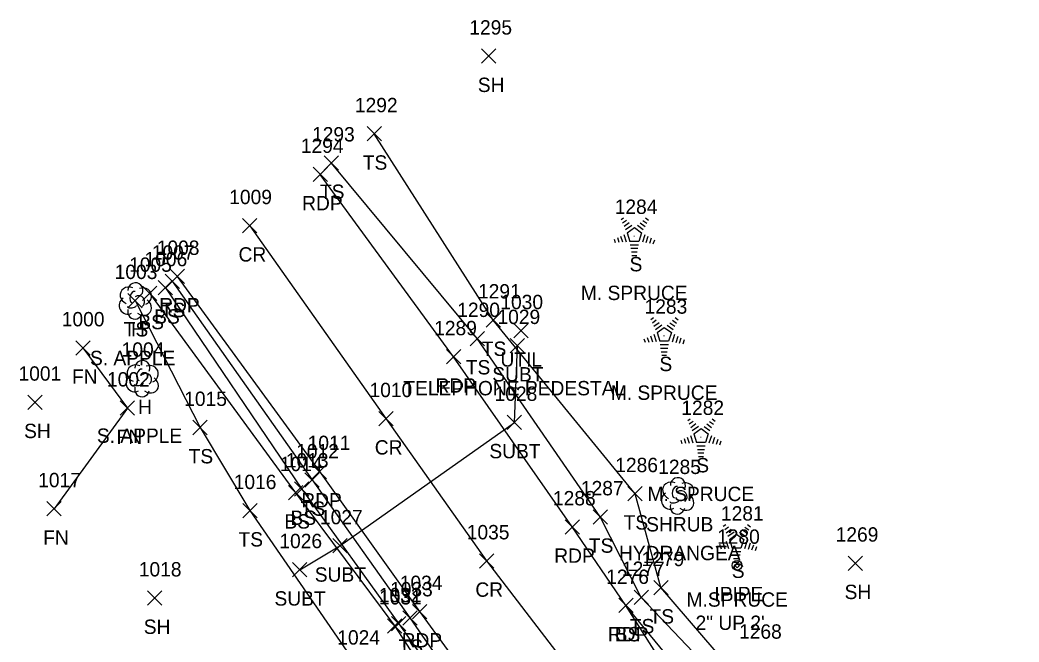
# Model space of a CAD drawing. Extents: x 1761340 to 1763889, y 696770 to 706023.
# Drawn here: x 1761339.7 to 1761478.8, y 701000.1 to 701086.8 of the extents above; entities that cross this region are included whole.
import ezdxf

# ---------------------------------------------------------------- set-up
doc = ezdxf.new("R2010")
doc.units = 0
for name, color, linetype in [('L_A', 7, 'Continuous'), ('L_C', 7, 'Continuous'), ('L_I', 7, 'Continuous'), ('L_TIC', 7, 'Continuous'), ('LELB', 7, 'Continuous'), ('LFNC', 7, 'Continuous'), ('LSH', 7, 'Continuous'), ('LTC', 7, 'Continuous'), ('LTD', 7, 'Continuous'), ('M_A', 7, 'Continuous'), ('M_C', 7, 'Continuous'), ('M_I', 7, 'Continuous'), ('MPIP', 7, 'Continuous'), ('P_A', 7, 'Continuous'), ('P_I', 7, 'Continuous'), ('P_TIC', 7, 'Continuous'), ('PET', 7, 'Continuous'), ('PRC', 7, 'Continuous'), ('U_A', 7, 'Continuous'), ('U_C', 7, 'Continuous'), ('U_I', 7, 'Continuous'), ('U_TIC', 7, 'Continuous'), ('UDEFAULT', 7, 'Continuous'), ('UT', 7, 'Continuous')]:
    doc.layers.add(name, color=color, linetype=linetype)

msp = doc.modelspace()

# ---------------------------------------------------------------- linework, layer by layer
at = {"layer": 'L_TIC'}
for points in [[(1761403.93, 701080.76), (1761405.93, 701082.76)], [(1761405.93, 701080.76), (1761403.93, 701082.76)], [(1761387.99, 701069.94), (1761389.99, 701071.94)], [(1761389.99, 701069.94), (1761387.99, 701071.94)], [(1761382.02, 701065.87), (1761384.02, 701067.87)], [(1761384.02, 701065.87), (1761382.02, 701067.87)], [(1761359.86, 701049.4), (1761361.86, 701051.4)], [(1761361.86, 701049.4), (1761359.86, 701051.4)], [(1761358.9, 701048.49), (1761360.9, 701050.49)], [(1761360.9, 701048.49), (1761358.9, 701050.49)], [(1761354.69, 701046.71), (1761356.69, 701048.71)], [(1761356.69, 701046.71), (1761354.69, 701048.71)], [(1761356.7, 701047.72), (1761358.7, 701049.72)], [(1761358.7, 701047.72), (1761356.7, 701049.72)], [(1761404.58, 701044), (1761406.58, 701046)], [(1761406.58, 701044), (1761404.58, 701046)], [(1761402.34, 701041.42), (1761404.34, 701043.42)], [(1761404.34, 701041.42), (1761402.34, 701043.42)], [(1761347.41, 701040.12), (1761349.41, 701042.12)], [(1761349.41, 701040.12), (1761347.41, 701042.12)], [(1761340.73, 701032.55), (1761342.73, 701034.55)], [(1761342.73, 701032.55), (1761340.73, 701034.55)], [(1761353.62, 701031.74), (1761355.62, 701033.74)], [(1761355.62, 701031.74), (1761353.62, 701033.74)], [(1761363.73, 701029.03), (1761365.73, 701031.03)], [(1761365.73, 701029.03), (1761363.73, 701031.03)], [(1761379.33, 701021.73), (1761381.33, 701023.73)], [(1761381.33, 701021.73), (1761379.33, 701023.73)], [(1761377.89, 701020.46), (1761379.89, 701022.46)], [(1761379.89, 701020.46), (1761377.89, 701022.46)], [(1761377.05, 701019.95), (1761379.05, 701021.95)], [(1761379.05, 701019.95), (1761377.05, 701021.95)], [(1761424.32, 701019.81), (1761426.32, 701021.81)], [(1761426.32, 701019.81), (1761424.32, 701021.81)], [(1761343.4, 701017.71), (1761345.4, 701019.71)], [(1761345.4, 701017.71), (1761343.4, 701019.71)], [(1761370.68, 701017.45), (1761372.68, 701019.45)], [(1761372.68, 701017.45), (1761370.68, 701019.45)], [(1761419.48, 701016.58), (1761421.48, 701018.58)], [(1761421.48, 701016.58), (1761419.48, 701018.58)], [(1761455.02, 701010.13), (1761457.02, 701012.13)], [(1761457.02, 701010.13), (1761455.02, 701012.13)], [(1761427.93, 701006.72), (1761429.93, 701008.72)], [(1761429.93, 701006.72), (1761427.93, 701008.72)], [(1761357.41, 701005.28), (1761359.41, 701007.28)], [(1761359.41, 701005.28), (1761357.41, 701007.28)], [(1761425.19, 701005.36), (1761427.19, 701007.36)], [(1761427.19, 701005.36), (1761425.19, 701007.36)], [(1761423.05, 701004.24), (1761425.05, 701006.24)], [(1761425.05, 701004.24), (1761423.05, 701006.24)], [(1761392.97, 701002.51), (1761394.97, 701004.51)], [(1761394.97, 701002.51), (1761392.97, 701004.51)], [(1761390.86, 701001.38), (1761392.86, 701003.38)], [(1761392.86, 701001.38), (1761390.86, 701003.38)], [(1761391.41, 701001.69), (1761393.41, 701003.69)], [(1761393.41, 701001.69), (1761391.41, 701003.69)]]:
    msp.add_lwpolyline(points, dxfattribs=at)
at = {"layer": 'LELB'}
for points in [[(1761440.34, 700994.46), (1761428.93, 701007.72), (1761425.32, 701020.81), (1761405.58, 701045), (1761388.99, 701070.94)], [(1761510.82, 700921.94), (1761487.03, 700937.99), (1761465.59, 700958.47), (1761457.07, 700967.17), (1761446.59, 700981.31), (1761437.01, 700994.98), (1761426.19, 701006.36), (1761420.48, 701017.58), (1761403.34, 701042.42), (1761383.02, 701066.87)], [(1761360.86, 701050.4), (1761380.33, 701022.73), (1761393.97, 701003.51), (1761412.73, 700976.45), (1761418.63, 700967.07), (1761415.65, 700964.75)], [(1761357.7, 701048.72), (1761378.05, 701020.95), (1761391.86, 701002.38), (1761410.48, 700973.63), (1761415.77, 700966.15)], [(1761359.9, 701049.49), (1761378.89, 701021.46), (1761392.41, 701002.69), (1761411.63, 700975.45), (1761416.96, 700967.25), (1761415.77, 700966.15)], [(1761355.69, 701047.71), (1761364.73, 701030.03), (1761371.68, 701018.45), (1761386.62, 700996.79), (1761392.6, 700989.5), (1761408.08, 700969.91), (1761415.65, 700964.75)], [(1761452.96, 700969.07), (1761433.93, 700993.22), (1761424.05, 701005.24)]]:
    msp.add_lwpolyline(points, dxfattribs=at)
at = {"layer": 'LFNC'}
msp.add_lwpolyline([(1761348.41, 701041.12), (1761354.62, 701032.74), (1761344.4, 701018.71)], dxfattribs=at)
at = {"layer": 'LSH'}
msp.add_line((1761431.24, 701020.55), (1761431.24, 701020.55), dxfattribs=at)
msp.add_line((1761431.24, 701020.55), (1761431.24, 701020.55), dxfattribs=at)
msp.add_arc((1761431.29, 701021.99), 1.05, 335.5272, 180.9563, dxfattribs=at)
for centre, major_axis, ratio, start_param, end_param in [((1761430.45, 701021.22), (1.21, -0.51), 0.895232, 1.570796, 4.712389), ((1761432.29, 701021.14), (-1.14, -0.48), 0.949671, 1.570796, 4.712389), ((1761430.16, 701019.84), (0.58, -1.04), 0.959034, 3.141593, 6.283185), ((1761431.04, 701021.01), (-0.208, -0.792), 0.645439, 3.141593, 6.283185), ((1761431.74, 701020.39), (-0.5, 0.667), 0.989748, 3.141593, 6.283185), ((1761432.24, 701019.72), (-1.09, 0.79), 0.841452, 1.570796, 4.712389), ((1761431.24, 701019.05), (0.26, 1.06), 0.942809, 1.570796, 4.712389), ((1761430.79, 701019.8), (-0.625, -0.083), 0.423636, 0, 3.141593)]:
    msp.add_ellipse(centre, major_axis=major_axis, ratio=ratio, start_param=start_param, end_param=end_param, dxfattribs=at)
at = {"layer": 'LTC'}
for p, q in [((1761423.37, 701058.99), (1761423.73, 701059.25)), ((1761423.58, 701058.53), (1761424.11, 701058.91)), ((1761423.79, 701058.06), (1761424.5, 701058.57)), ((1761424, 701057.6), (1761424.88, 701058.23)), ((1761425.66, 701058.19), (1761426.47, 701057.6)), ((1761426.03, 701058.54), (1761426.71, 701058.04)), ((1761426.4, 701058.88), (1761426.95, 701058.49)), ((1761426.77, 701059.23), (1761427.19, 701058.93)), ((1761423.77, 701056.92), (1761424.1, 701055.9)), ((1761424.23, 701057.14), (1761425.24, 701057.87)), ((1761424.23, 701057.14), (1761424.61, 701055.95)), ((1761425.24, 701057.87), (1761426.24, 701057.15)), ((1761426.24, 701057.15), (1761425.84, 701055.95)), ((1761426.67, 701056.88), (1761426.34, 701055.84)), ((1761422.41, 701056.27), (1761422.56, 701055.8)), ((1761422.86, 701056.49), (1761423.07, 701055.84)), ((1761423.32, 701056.7), (1761423.59, 701055.87)), ((1761425.84, 701055.95), (1761424.61, 701055.95)), ((1761425.81, 701055.45), (1761424.66, 701055.45)), ((1761427.12, 701056.63), (1761426.83, 701055.74)), ((1761427.56, 701056.38), (1761427.33, 701055.65)), ((1761428.01, 701056.13), (1761427.82, 701055.55)), ((1761425.72, 701054.95), (1761424.73, 701054.95)), ((1761425.64, 701054.45), (1761424.81, 701054.45)), ((1761425.56, 701053.95), (1761424.88, 701053.95)), ((1761427.53, 701045.09), (1761427.89, 701045.34)), ((1761427.74, 701044.62), (1761428.27, 701045.01)), ((1761427.95, 701044.16), (1761428.66, 701044.67)), ((1761428.16, 701043.69), (1761429.04, 701044.33)), ((1761429.82, 701044.28), (1761430.63, 701043.69)), ((1761430.19, 701044.63), (1761430.87, 701044.14)), ((1761430.56, 701044.98), (1761431.11, 701044.58)), ((1761430.93, 701045.33), (1761431.35, 701045.02)), ((1761427.93, 701043.02), (1761428.26, 701042)), ((1761428.39, 701043.24), (1761429.4, 701043.97)), ((1761428.39, 701043.24), (1761428.77, 701042.04)), ((1761429.4, 701043.97), (1761430.4, 701043.24)), ((1761430.4, 701043.24), (1761430, 701042.04)), ((1761430.83, 701042.97), (1761430.5, 701041.93)), ((1761426.57, 701042.37), (1761426.72, 701041.9)), ((1761427.02, 701042.58), (1761427.23, 701041.93)), ((1761427.48, 701042.8), (1761427.75, 701041.96)), ((1761430, 701042.04), (1761428.77, 701042.04)), ((1761429.97, 701041.54), (1761428.82, 701041.54)), ((1761431.28, 701042.72), (1761430.99, 701041.84)), ((1761431.72, 701042.47), (1761431.49, 701041.74)), ((1761432.17, 701042.22), (1761431.98, 701041.65)), ((1761429.88, 701041.04), (1761428.89, 701041.04)), ((1761429.8, 701040.54), (1761428.97, 701040.54)), ((1761429.72, 701040.04), (1761429.04, 701040.04)), ((1761432.66, 701030.99), (1761433.01, 701031.24)), ((1761432.87, 701030.52), (1761433.4, 701030.9)), ((1761433.08, 701030.05), (1761433.78, 701030.57)), ((1761435.31, 701030.53), (1761435.99, 701030.04)), ((1761435.68, 701030.88), (1761436.23, 701030.48)), ((1761436.06, 701031.23), (1761436.47, 701030.92)), ((1761433.06, 701028.91), (1761433.39, 701027.9)), ((1761433.29, 701029.59), (1761434.16, 701030.23)), ((1761433.51, 701029.13), (1761434.52, 701029.87)), ((1761433.51, 701029.13), (1761433.9, 701027.94)), ((1761434.52, 701029.87), (1761435.52, 701029.14)), ((1761434.94, 701030.18), (1761435.75, 701029.59)), ((1761435.52, 701029.14), (1761435.13, 701027.94)), ((1761431.69, 701028.26), (1761431.84, 701027.8)), ((1761432.15, 701028.48), (1761432.36, 701027.83)), ((1761432.6, 701028.7), (1761432.87, 701027.86)), ((1761435.13, 701027.94), (1761433.9, 701027.94)), ((1761435.96, 701028.87), (1761435.62, 701027.83)), ((1761436.4, 701028.62), (1761436.11, 701027.74)), ((1761436.85, 701028.37), (1761436.61, 701027.64)), ((1761437.29, 701028.12), (1761437.1, 701027.55)), ((1761435.09, 701027.44), (1761433.95, 701027.44)), ((1761435.01, 701026.94), (1761434.02, 701026.94)), ((1761434.92, 701026.44), (1761434.09, 701026.44)), ((1761434.84, 701025.94), (1761434.16, 701025.94)), ((1761437.61, 701016.27), (1761437.96, 701016.53)), ((1761441.01, 701016.51), (1761441.42, 701016.21)), ((1761437.82, 701015.81), (1761438.35, 701016.19)), ((1761438.03, 701015.34), (1761438.73, 701015.85)), ((1761438.24, 701014.88), (1761439.11, 701015.51)), ((1761438.46, 701014.42), (1761439.47, 701015.16)), ((1761439.47, 701015.16), (1761440.47, 701014.43)), ((1761439.89, 701015.47), (1761440.7, 701014.88)), ((1761440.26, 701015.82), (1761440.94, 701015.32)), ((1761440.63, 701016.17), (1761441.18, 701015.77)), ((1761437.09, 701013.77), (1761437.31, 701013.12)), ((1761437.55, 701013.99), (1761437.82, 701013.15)), ((1761438.01, 701014.2), (1761438.34, 701013.18)), ((1761438.46, 701014.42), (1761438.85, 701013.23)), ((1761440.47, 701014.43), (1761440.08, 701013.23)), ((1761440.91, 701014.16), (1761440.57, 701013.12)), ((1761441.35, 701013.91), (1761441.06, 701013.03)), ((1761441.8, 701013.66), (1761441.56, 701012.93)), ((1761436.64, 701013.55), (1761436.79, 701013.08)), ((1761440.08, 701013.23), (1761438.85, 701013.23)), ((1761440.04, 701012.73), (1761438.89, 701012.73)), ((1761439.96, 701012.23), (1761438.97, 701012.23)), ((1761442.24, 701013.41), (1761442.05, 701012.84)), ((1761439.87, 701011.73), (1761439.04, 701011.73)), ((1761439.79, 701011.23), (1761439.11, 701011.23))]:
    msp.add_line(p, q, dxfattribs=at)
at = {"layer": 'LTD'}
for p, q in [((1761355.69, 701047.71), (1761355.69, 701047.71)), ((1761355.69, 701047.71), (1761355.69, 701047.71)), ((1761356.66, 701036.89), (1761356.66, 701036.89)), ((1761356.66, 701036.89), (1761356.66, 701036.89))]:
    msp.add_line(p, q, dxfattribs=at)
for centre in [(1761355.74, 701049.14), (1761356.71, 701038.32)]:
    msp.add_arc(centre, 1.05, 335.5272, 180.9563, dxfattribs=at)
for centre, major_axis, ratio, start_param, end_param in [((1761354.9, 701048.38), (1.21, -0.51), 0.895232, 1.570796, 4.712389), ((1761355.49, 701048.17), (-0.208, -0.792), 0.645439, 3.141593, 6.283185), ((1761356.19, 701047.54), (-0.5, 0.667), 0.989748, 3.141593, 6.283185), ((1761356.74, 701048.29), (-1.14, -0.48), 0.949671, 1.570796, 4.712389), ((1761354.61, 701047), (0.58, -1.04), 0.959034, 3.141593, 6.283185), ((1761355.24, 701046.96), (-0.625, -0.083), 0.423636, 0, 3.141593), ((1761356.69, 701046.88), (-1.09, 0.79), 0.841452, 1.570796, 4.712389), ((1761355.69, 701046.21), (0.26, 1.06), 0.942809, 1.570796, 4.712389), ((1761355.87, 701037.55), (1.21, -0.51), 0.895232, 1.570796, 4.712389), ((1761357.7, 701037.47), (-1.14, -0.48), 0.949671, 1.570796, 4.712389), ((1761356.45, 701037.35), (-0.208, -0.792), 0.645439, 3.141593, 6.283185), ((1761357.16, 701036.72), (-0.5, 0.667), 0.989748, 3.141593, 6.283185), ((1761355.58, 701036.18), (0.58, -1.04), 0.959034, 3.141593, 6.283185), ((1761356.2, 701036.14), (-0.625, -0.083), 0.423636, 0, 3.141593), ((1761357.66, 701036.05), (-1.09, 0.79), 0.841452, 1.570796, 4.712389), ((1761356.66, 701035.39), (0.26, 1.06), 0.942809, 1.570796, 4.712389)]:
    msp.add_ellipse(centre, major_axis=major_axis, ratio=ratio, start_param=start_param, end_param=end_param, dxfattribs=at)
at = {"layer": 'MPIP'}
msp.add_lwpolyline([(1761439.86, 701010.83), (1761439.53, 701011.16), (1761439.2, 701010.83), (1761439.53, 701010.5)], close=True, dxfattribs=at)
msp.add_circle((1761439.53, 701010.83), 0.667, dxfattribs=at)
at = {"layer": 'P_TIC'}
for points in [[(1761380.47, 701064.28), (1761382.47, 701066.28)], [(1761382.47, 701064.28), (1761380.47, 701066.28)], [(1761370.66, 701057.14), (1761372.66, 701059.14)], [(1761372.66, 701057.14), (1761370.66, 701059.14)], [(1761360.55, 701050.07), (1761362.55, 701052.07)], [(1761362.55, 701050.07), (1761360.55, 701052.07)], [(1761399.04, 701038.88), (1761401.04, 701040.88)], [(1761401.04, 701038.88), (1761399.04, 701040.88)], [(1761389.63, 701030.26), (1761391.63, 701032.26)], [(1761391.63, 701030.26), (1761389.63, 701032.26)], [(1761380.35, 701022.89), (1761382.35, 701024.89)], [(1761382.35, 701022.89), (1761380.35, 701024.89)], [(1761415.58, 701015.18), (1761417.58, 701017.18)], [(1761417.58, 701015.18), (1761415.58, 701017.18)], [(1761403.65, 701010.45), (1761405.65, 701012.45)], [(1761405.65, 701010.45), (1761403.65, 701012.45)], [(1761394.32, 701003.39), (1761396.32, 701005.39)], [(1761396.32, 701003.39), (1761394.32, 701005.39)], [(1761423.05, 701004.24), (1761425.05, 701006.24)], [(1761425.05, 701004.24), (1761423.05, 701006.24)]]:
    msp.add_lwpolyline(points, dxfattribs=at)
at = {"layer": 'PET'}
for points in [[(1761565.69, 700887.32), (1761551.93, 700894.01), (1761537.2, 700902.21), (1761507.2, 700921.56), (1761485.83, 700936.45), (1761463.82, 700956.86), (1761451.66, 700968.66), (1761442.59, 700979.07), (1761431.29, 700993.83), (1761424.05, 701005.24), (1761416.58, 701016.18), (1761400.04, 701039.88), (1761381.47, 701065.28)], [(1761361.55, 701051.07), (1761381.35, 701023.89), (1761395.32, 701004.39), (1761414.57, 700977.92), (1761433.71, 700954.24), (1761453.66, 700932.57), (1761475.8, 700912.49), (1761486.98, 700903.81), (1761500.92, 700894.3), (1761527.65, 700879.06), (1761551.01, 700866.82), (1761575.84, 700857.11)]]:
    msp.add_lwpolyline(points, dxfattribs=at)
at = {"layer": 'PRC'}
msp.add_lwpolyline([(1761371.66, 701058.14), (1761390.63, 701031.26), (1761404.65, 701011.45), (1761424.14, 700986), (1761443.93, 700962.2), (1761463.21, 700942.49), (1761486.68, 700921.95), (1761508.06, 700906.42), (1761533.51, 700890.82), (1761557.04, 700878.89), (1761580.26, 700869.03), (1761600.69, 700862.06)], dxfattribs=at)
at = {"layer": 'U_TIC'}
for points in [[(1761407.94, 701040.44), (1761409.94, 701042.44)], [(1761409.94, 701040.44), (1761407.94, 701042.44)], [(1761407.53, 701029.74), (1761409.53, 701031.74)], [(1761409.53, 701029.74), (1761407.53, 701031.74)], [(1761383.21, 701012.55), (1761385.21, 701014.55)], [(1761385.21, 701012.55), (1761383.21, 701014.55)], [(1761377.61, 701009.22), (1761379.61, 701011.22)], [(1761379.61, 701009.22), (1761377.61, 701011.22)]]:
    msp.add_lwpolyline(points, dxfattribs=at)
at = {"layer": 'UDEFAULT'}
for points in [[(1761408.42, 701042.51), (1761410.42, 701044.51)], [(1761410.42, 701042.51), (1761408.42, 701044.51)]]:
    msp.add_lwpolyline(points, dxfattribs=at)
at = {"layer": 'UT'}
msp.add_lwpolyline([(1761378.61, 701010.22), (1761384.21, 701013.55), (1761408.53, 701030.74), (1761408.94, 701041.44)], dxfattribs=at)

# ---------------------------------------------------------------- texts
at = {"layer": 'L_A'}
for s, p in [('SH', (1761403.42, 701076.76)), ('TS', (1761387.4, 701065.94)), ('TS', (1761381.43, 701061.87)), ('S', (1761424.56, 701051.78)), ('TS', (1761359.27, 701045.4)), ('BS', (1761356.14, 701043.72)), ('BS', (1761358.34, 701044.49)), ('TS', (1761354.1, 701042.71)), ('H', (1761355.13, 701042.71)), ('TS', (1761403.98, 701040)), ('TS', (1761401.75, 701037.42)), ('S', (1761428.72, 701037.88)), ('FN', (1761346.89, 701036.12)), ('H', (1761356.1, 701031.89)), ('SH', (1761340.22, 701028.55)), ('FN', (1761353.1, 701027.74)), ('TS', (1761363.14, 701025.03)), ('S', (1761433.85, 701023.78)), ('TS', (1761378.74, 701017.73)), ('BS', (1761376.49, 701015.95)), ('BS', (1761377.33, 701016.46)), ('TS', (1761423.73, 701015.81)), ('SHRUB', (1761426.87, 701015.55)), ('FN', (1761342.88, 701013.71)), ('TS', (1761370.09, 701013.45)), ('TS', (1761418.89, 701012.58)), ('S', (1761438.8, 701009.07)), ('SH', (1761454.51, 701006.13)), ('TS', (1761427.34, 701002.72)), ('SH', (1761356.89, 701001.28)), ('TS', (1761424.6, 701001.36)), ('BS', (1761422.49, 701000.24)), ('TS', (1761392.38, 700998.51))]:
    msp.add_text(s, height=2, dxfattribs=at).set_placement(p)
at = {"layer": 'L_C'}
for s, p in [('M. SPRUCE', (1761417.78, 701047.78)), ('S. APPLE', (1761349.4, 701038.71)), ('M. SPRUCE', (1761421.94, 701033.88)), ('S. APPLE', (1761350.36, 701027.89)), ('M. SPRUCE', (1761427.06, 701019.78)), ('HYDRANGEA', (1761423.08, 701011.55)), ('M.SPRUCE', (1761432.5, 701005.07))]:
    msp.add_text(s, height=2, dxfattribs=at).set_placement(p)
at = {"layer": 'L_I'}
for s, p in [('1295', (1761402.24, 701084.76)), ('1292', (1761386.3, 701073.94)), ('1293', (1761380.33, 701069.87)), ('1284', (1761422.49, 701059.78)), ('1007', (1761358.01, 701053.4)), ('1006', (1761357, 701052.49)), ('1003', (1761352.84, 701050.71)), ('1003', (1761352.84, 701050.71)), ('1005', (1761354.85, 701051.72)), ('1291', (1761403.45, 701048)), ('1290', (1761400.56, 701045.42)), ('1283', (1761426.65, 701045.88)), ('1000', (1761345.47, 701044.12)), ('1004', (1761353.81, 701039.89)), ('1001', (1761339.45, 701036.55)), ('1002', (1761351.77, 701035.74)), ('1015', (1761362.53, 701033.03)), ('1282', (1761431.77, 701031.78)), ('1012', (1761378.12, 701025.73)), ('1013', (1761376.68, 701024.46)), ('1014', (1761375.84, 701023.95)), ('1286', (1761422.57, 701023.81)), ('1285', (1761428.55, 701023.55)), ('1017', (1761342.19, 701021.71)), ('1016', (1761369.42, 701021.45)), ('1287', (1761417.78, 701020.58)), ('1281', (1761437.29, 701017.07)), ('1269', (1761453.27, 701014.13)), ('1279', (1761426.23, 701010.72)), ('1018', (1761356.2, 701009.28)), ('1277', (1761423.5, 701009.36)), ('1276', (1761421.3, 701008.24)), ('1033', (1761391.2, 701006.51)), ('1032', (1761389.63, 701005.69)), ('1031', (1761389.66, 701005.38)), ('1268', (1761439.81, 701000.61)), ('1024', (1761383.85, 700999.79))]:
    msp.add_text(s, height=2, dxfattribs=at).set_placement(p)
at = {"layer": 'LTC'}
for p in [(1761425.12, 701056.89), (1761429.28, 701042.98), (1761434.4, 701028.88), (1761439.35, 701014.17)]:
    msp.add_text('.', height=1.04, rotation=270, dxfattribs=at).set_placement(p)
at = {"layer": 'M_A'}
msp.add_text('IPIPE', height=2, dxfattribs=at).set_placement((1761436.36, 701005.83))
at = {"layer": 'M_C'}
msp.add_text('2" UP 2\'', height=2, dxfattribs=at).set_placement((1761433.75, 701001.83))
at = {"layer": 'M_I'}
msp.add_text('1280', height=2, dxfattribs=at).set_placement((1761436.75, 701013.83))
at = {"layer": 'P_A'}
for s, p in [('RDP', (1761378.95, 701060.28)), ('CR', (1761370.09, 701053.14)), ('RDP', (1761359.04, 701046.07)), ('RDP', (1761397.53, 701034.88)), ('CR', (1761389.07, 701026.26)), ('RDP', (1761378.84, 701018.89)), ('RDP', (1761414.07, 701011.18)), ('CR', (1761403.08, 701006.45)), ('RDP', (1761392.81, 700999.39)), ('RDP', (1761421.54, 701000.24))]:
    msp.add_text(s, height=2, dxfattribs=at).set_placement(p)
at = {"layer": 'P_I'}
for s, p in [('1294', (1761378.77, 701068.28)), ('1009', (1761368.8, 701061.14)), ('1008', (1761358.7, 701054.07)), ('1289', (1761397.34, 701042.88)), ('1010', (1761388.34, 701034.26)), ('1011', (1761379.72, 701026.89)), ('1288', (1761413.89, 701019.18)), ('1035', (1761401.88, 701014.45)), ('1276', (1761421.3, 701008.24)), ('1034', (1761392.55, 701007.39))]:
    msp.add_text(s, height=2, dxfattribs=at).set_placement(p)
at = {"layer": 'U_A'}
for s, p in [('UTIL', (1761406.58, 701038.51)), ('SUBT', (1761405.44, 701036.44)), ('SUBT', (1761405.03, 701025.74)), ('SUBT', (1761380.71, 701008.55)), ('SUBT', (1761375.1, 701005.22))]:
    msp.add_text(s, height=2, dxfattribs=at).set_placement(p)
at = {"layer": 'U_C'}
msp.add_text('TELEPHONE PEDESTAL', height=2, dxfattribs=at).set_placement((1761393.04, 701034.51))
at = {"layer": 'U_I'}
for s, p in [('1030', (1761406.56, 701046.51)), ('1029', (1761406.16, 701044.44)), ('1028', (1761405.76, 701033.74)), ('1027', (1761381.44, 701016.55)), ('1026', (1761375.78, 701013.22))]:
    msp.add_text(s, height=2, dxfattribs=at).set_placement(p)

doc.saveas('drawing.dxf')
